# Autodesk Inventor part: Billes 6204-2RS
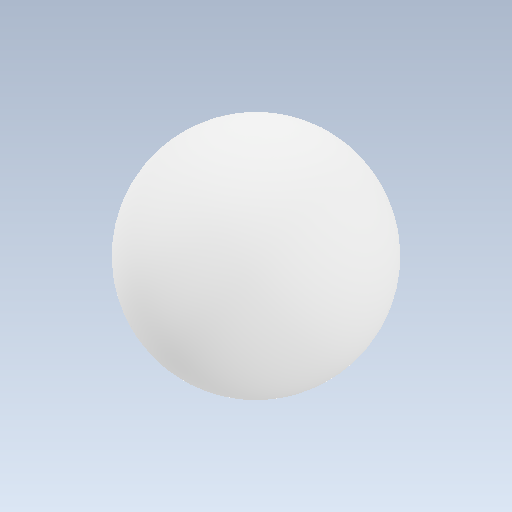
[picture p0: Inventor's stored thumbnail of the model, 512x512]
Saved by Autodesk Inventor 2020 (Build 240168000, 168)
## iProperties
Created: 2003-07
Part Number: Billes 6204-2RS
Material: Générique
Document SubType Name: Modeling
Designer: Bruno
Density: 1 g/cm^3
Appearance: Par défaut
Author: Bruno
Sending System: SolidWorks 2011
Last Author: frederic
Last Saved: 2012-02-20
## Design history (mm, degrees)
feature "Base-Révolution"
node "Solide1"
